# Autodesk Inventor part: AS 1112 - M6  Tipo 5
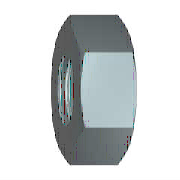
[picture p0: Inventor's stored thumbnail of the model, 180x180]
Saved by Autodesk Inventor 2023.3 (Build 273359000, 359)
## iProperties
Created: 2022-02
Part Number: AS 1112 - M6  Tipo 5
Material: Acciaio, Dolce
Description: Dadi esagonali metrici ISO, inclusi dadi sottili, dadi con intaglio e dadi a corona
Document SubType Name: Modeling
Standard: AS 1112
Designer: x300
Standards Organization: AS
Language: it-IT
Size Designation: M6  Tipo 5
Categories: <MemberInstance><Categories><Category DisplayName="Elementi di fissaggio" InternalName="e4da775c-781d-43d5-af7c-5136215cf5a6" Mnemonic="FSTN"><Category DisplayN
Density: 7.85 g/cm^3
Appearance: Semilucidato
IsCustomPart: 0
Author: x300
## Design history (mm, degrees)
sketch "Schizzo1"
  geometry: L1 (-5.774, 0)-(-2.887, 5); L2 (-2.887, 5)-(2.887, 5); L3 (2.887, 5)-(5.774, 0); L4 (5.774, 0)-(2.887, -5); L5 (2.887, -5)-(-2.887, -5); L6 (-2.887, -5)-(-5.774, 0); 2 further points
  constraints: 12 end point, 1 coincident, 1 horizontal, 11 other
  dimensions: "d0" = 11.54701 distance of L3.end L1.start (= 1.1547 x SW)
extrude "Corpo" new body sketch "Schizzo1" distance "d1" = 5.2 (= KOH); taper "d2" = 0 deg
sketch "Schizzo2"
  geometry: L1 (0, 2.887)-(0, 5.774) reference; L2 (0, 5.774)-(5.2, 5.774) reference; L3 (5.2, 2.887)-(5.2, 5.774) reference; L4 (-1.04, 0)-(6.24, 0) reference; L5 (0.447, 5.774)-(0, 5); L6 (4.753, 5.774)-(5.2, 5)
  constraints: 4 end point, 4 point on line
  dimensions: "d3" = 30 deg angle of L1 L5 (= ANG1); "d4" = 30 deg angle of L3 L6 (= ANG2); "d5" = 10 diameter of L5.end L4 (= SW0); "d6" = 10 diameter of L6.end L4 (= SW01)
revolve "Smusso1" sketch "Schizzo2" stored, may be unused: angle "d7" = 90 deg
sketch "Schizzo3"
  geometry: A1 r 5 centre (0, 0) between (-2.5, -4.33) and (2.5, -4.33) reference; 1 further point
  constraints: 1 coincident
hole "Filettatura" sketch "Schizzo3" at (0, 0) diameter "d25" = 4.917; stored, may be unused: countersink angle "d29" = 82 deg, drill point angle "d31" = 118 deg; dims "d26" = 6, "d27" = 4, "d28" = 2, "d30" = 8
workaxis "Work Axis1"
workplane "Work Plane1"
body "Solid1"
chamfer "Smusso2" distance "d8" = 0.54127 (= -0.5 x GD1 + 0.5 x NND); stored, may be unused: angle "d9" = 30 deg, second distance "d40" = 0.54127 (= -0.5 x GD1 + 0.5 x NND)
chamfer "Smusso3" distance "d10" = 0.54127 (= -0.5 x GD1 + 0.5 x NND); stored, may be unused: angle "d11" = 30 deg, second distance "d41" = 0.54127 (= -0.5 x GD1 + 0.5 x NND)
other parameters: "ANG1" = 30 deg [user parameter; used in 1 equation term], "ANG2" = 30 deg [user parameter; used in 1 equation term], "NND" = 6 [user parameter; used in 4 equation terms], "KOH" = 5.2 [user parameter; used in 1 equation term], "SW0" = 10 (= SW) [user parameter; used in 1 equation term], "SW01" = 10 (= SW) [user parameter; used in 1 equation term], "GD1" = 4.91747 (computed from THREADDIA, PTC, TOA) [user parameter; used in 4 equation terms], "d13" = 0, "d14" = 0, "d39" = 0, "d42" = 0, "GUL" = 0.54127 (= 0.541266 x PTC) [user parameter], "WFT" = 0.5 [user parameter], "THREADDIA" = 6 [user parameter; used in 1 equation term], "TOA" = 30 deg [user parameter; used in 1 equation term], "PTC" = 1 [user parameter; used in 4 equation terms], "E0" = 11.55 (= 1.155 x SW) [user parameter], "GAL" = 0.54127 (= 0.541266 x PTC) [user parameter]
